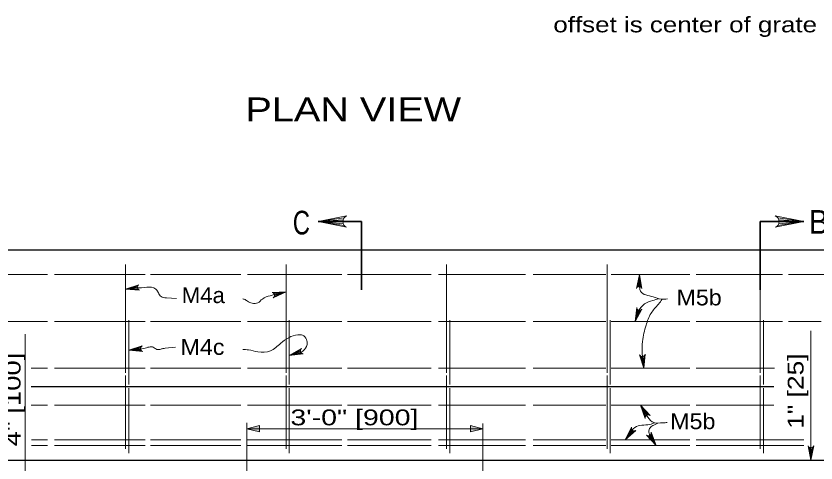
# Model space of a CAD drawing. Extents: x -1431.2 to -1397.2, y -1045.1 to -1001.1.
# Drawn here: x -1422.47 to -1414.42, y -1016.52 to -1012.02 of the extents above; entities that cross this region are included whole.
import ezdxf

# ---------------------------------------------------------------- set-up
doc = ezdxf.new("R2010")
doc.units = 0
doc.header["$LTSCALE"] = 0.064
doc.layers.add('1', color=7, linetype='Continuous', lineweight=13)

msp = doc.modelspace()

# ---------------------------------------------------------------- hatches: boundary and pattern name
at = {"layer": '1'}
for points in [[(-1420.02092, -1016.204), (-1420.147, -1016.1725), (-1420.02092, -1016.14092)], [(-1417.90083, -1016.14092), (-1417.77475, -1016.1725), (-1417.90083, -1016.204)]]:
    msp.add_hatch(color=256, dxfattribs=at).paths.add_polyline_path(points)

# ---------------------------------------------------------------- linework, layer by layer
for p, q in [((-1419.172, -1014.05292), (-1419.43075, -1014.08908)), ((-1419.18075, -1014.07083), (-1419.43075, -1014.08908)), ((-1414.80717, -1014.05292), (-1414.54842, -1014.08908)), ((-1414.79842, -1014.07083), (-1414.54842, -1014.08908)), ((-1419.18342, -1014.08908), (-1419.43075, -1014.08908)), ((-1419.17883, -1014.11233), (-1419.43075, -1014.08908)), ((-1419.16892, -1014.12908), (-1419.43075, -1014.08908)), ((-1414.81025, -1014.12908), (-1414.54842, -1014.08908)), ((-1414.80033, -1014.11233), (-1414.54842, -1014.08908)), ((-1414.79575, -1014.08908), (-1414.54842, -1014.08908)), ((-1421.36758, -1014.51992), (-1421.36758, -1015.60892)), ((-1419.75375, -1014.51992), (-1419.75375, -1015.60892)), ((-1416.52608, -1014.51992), (-1416.52608, -1015.60892)), ((-1414.98508, -1014.51992), (-1414.98508, -1015.60892)), ((-1423.05333, -1014.62258), (-1422.15367, -1014.62258)), ((-1422.08258, -1014.62258), (-1421.17017, -1014.62258)), ((-1421.119, -1014.62258), (-1420.20733, -1014.62258)), ((-1420.14183, -1014.62258), (-1419.19433, -1014.62258)), ((-1419.13675, -1014.62258), (-1418.29542, -1014.62258)), ((-1418.22033, -1014.62258), (-1417.34475, -1014.62258)), ((-1417.27042, -1014.62258), (-1416.537, -1014.62258)), ((-1416.485, -1014.62258), (-1415.69483, -1014.62258)), ((-1416.22192, -1014.74908), (-1416.19967, -1014.62258)), ((-1416.21367, -1014.7445), (-1416.19967, -1014.62258)), ((-1416.20233, -1014.7425), (-1416.19967, -1014.62258)), ((-1416.1935, -1014.744), (-1416.19967, -1014.62258)), ((-1416.18483, -1014.7485), (-1416.19967, -1014.62258)), ((-1415.631, -1014.62258), (-1414.76158, -1014.62258)), ((-1414.70258, -1014.62258), (-1413.85083, -1014.62258)), ((-1421.24533, -1014.73617), (-1421.36758, -1014.76983)), ((-1421.24842, -1014.74533), (-1421.36758, -1014.76983)), ((-1421.2485, -1014.75425), (-1421.36758, -1014.76983)), ((-1421.24492, -1014.76517), (-1421.36758, -1014.76983)), ((-1421.23908, -1014.77258), (-1421.36758, -1014.76983)), ((-1419.88183, -1014.80683), (-1419.75375, -1014.79658)), ((-1419.87533, -1014.81367), (-1419.75375, -1014.79658)), ((-1419.87192, -1014.8425), (-1419.75375, -1014.79658)), ((-1419.8705, -1014.82408), (-1419.75375, -1014.79658)), ((-1419.86983, -1014.83308), (-1419.75375, -1014.79658)), ((-1420.9565, -1014.85442), (-1420.85533, -1014.86242)), ((-1416.222, -1014.96883), (-1416.2425, -1015.094)), ((-1416.215, -1014.9755), (-1416.2425, -1015.094)), ((-1416.18625, -1014.97842), (-1416.2425, -1015.094)), ((-1416.20692, -1014.97933), (-1416.2425, -1015.094)), ((-1416.1955, -1014.98067), (-1416.2425, -1015.094)), ((-1423.05333, -1015.094), (-1422.15367, -1015.094)), ((-1422.08258, -1015.094), (-1421.17017, -1015.094)), ((-1421.33592, -1015.07958), (-1421.33592, -1015.72717)), ((-1421.119, -1015.094), (-1420.20733, -1015.094)), ((-1420.14183, -1015.094), (-1419.19433, -1015.094)), ((-1419.72208, -1015.07958), (-1419.72208, -1015.72717)), ((-1419.13675, -1015.094), (-1418.29542, -1015.094)), ((-1418.22033, -1015.094), (-1417.34475, -1015.094)), ((-1417.27042, -1015.094), (-1416.537, -1015.094)), ((-1416.49442, -1015.07958), (-1416.49442, -1015.72717)), ((-1416.485, -1015.094), (-1415.69483, -1015.094)), ((-1415.631, -1015.094), (-1414.76158, -1015.094)), ((-1414.95325, -1015.07958), (-1414.95325, -1015.72717)), ((-1414.70258, -1015.094), (-1414.37258, -1015.094)), ((-1414.47525, -1015.18883), (-1414.47525, -1016.48792)), ((-1422.37767, -1016.85133), (-1422.37767, -1015.22133)), ((-1421.21283, -1015.35125), (-1421.33592, -1015.38167)), ((-1421.21617, -1015.36033), (-1421.33592, -1015.38167)), ((-1420.96958, -1015.36383), (-1420.86583, -1015.35258)), ((-1421.2165, -1015.36925), (-1421.33592, -1015.38167)), ((-1421.21317, -1015.38025), (-1421.33592, -1015.38167)), ((-1421.2075, -1015.38792), (-1421.33592, -1015.38167)), ((-1419.60792, -1015.37992), (-1419.72208, -1015.435)), ((-1419.60933, -1015.3895), (-1419.72208, -1015.435)), ((-1419.60783, -1015.39833), (-1419.72208, -1015.435)), ((-1419.60225, -1015.40842), (-1419.72208, -1015.435)), ((-1419.59517, -1015.41467), (-1419.72208, -1015.435)), ((-1416.18658, -1015.44125), (-1416.1545, -1015.56392)), ((-1416.17742, -1015.4445), (-1416.1545, -1015.56392)), ((-1416.1685, -1015.44475), (-1416.1545, -1015.56392)), ((-1416.15758, -1015.44117), (-1416.1545, -1015.56392)), ((-1416.15008, -1015.4355), (-1416.1545, -1015.56392)), ((-1422.3185, -1015.56392), (-1422.15367, -1015.56392)), ((-1422.08258, -1015.56392), (-1421.17017, -1015.56392)), ((-1421.119, -1015.56392), (-1420.20733, -1015.56392)), ((-1420.14183, -1015.56392), (-1419.19433, -1015.56392)), ((-1419.13675, -1015.56392), (-1418.29542, -1015.56392)), ((-1418.22033, -1015.56392), (-1417.34475, -1015.56392)), ((-1417.27042, -1015.56392), (-1416.537, -1015.56392)), ((-1416.485, -1015.56392), (-1415.69483, -1015.56392)), ((-1415.631, -1015.56392), (-1414.84108, -1015.56392)), ((-1421.36758, -1015.63667), (-1421.36758, -1016.37583)), ((-1419.75375, -1015.63667), (-1419.75375, -1016.37583)), ((-1418.13992, -1015.63667), (-1418.13992, -1016.37583)), ((-1416.52608, -1015.63667), (-1416.52608, -1016.37583)), ((-1414.98508, -1015.63667), (-1414.98508, -1016.37583)), ((-1421.33592, -1015.76483), (-1421.33592, -1016.41842)), ((-1419.72208, -1015.76483), (-1419.72208, -1016.41842)), ((-1418.10825, -1015.76483), (-1418.10825, -1016.41842)), ((-1416.49442, -1015.76483), (-1416.49442, -1016.41842)), ((-1414.95325, -1015.76483), (-1414.95325, -1016.41842)), ((-1422.3185, -1015.93567), (-1422.15367, -1015.93567)), ((-1422.08258, -1015.93567), (-1421.17017, -1015.93567)), ((-1421.119, -1015.93567), (-1420.20733, -1015.93567)), ((-1420.14183, -1015.93567), (-1419.19433, -1015.93567)), ((-1419.13675, -1015.93567), (-1418.29542, -1015.93567)), ((-1418.22033, -1015.93567), (-1417.34475, -1015.93567)), ((-1417.27042, -1015.93567), (-1416.537, -1015.93567)), ((-1416.485, -1015.93567), (-1415.69483, -1015.93567)), ((-1416.12725, -1016.03767), (-1416.19042, -1015.93567)), ((-1416.13567, -1016.04542), (-1416.19042, -1015.93567)), ((-1416.14, -1016.05383), (-1416.19042, -1015.93567)), ((-1416.11892, -1016.03408), (-1416.19042, -1015.93567)), ((-1416.10933, -1016.03317), (-1416.19042, -1015.93567)), ((-1415.631, -1015.93567), (-1414.84833, -1015.93567)), ((-1420.147, -1016.69683), (-1420.147, -1016.11292)), ((-1418.73825, -1016.1725), (-1420.147, -1016.1725)), ((-1418.73825, -1016.1725), (-1417.77475, -1016.1725)), ((-1417.77475, -1016.70442), (-1417.77475, -1016.11833)), ((-1416.28025, -1016.17417), (-1416.34225, -1016.28475)), ((-1416.27592, -1016.18283), (-1416.34225, -1016.28475)), ((-1416.26967, -1016.18917), (-1416.34225, -1016.28475)), ((-1416.25925, -1016.19433), (-1416.34225, -1016.28475)), ((-1416.24992, -1016.19542), (-1416.34225, -1016.28475)), ((-1416.11267, -1016.24275), (-1416.03175, -1016.34033)), ((-1416.103, -1016.24175), (-1416.03175, -1016.34033)), ((-1416.09475, -1016.23825), (-1416.03175, -1016.34033)), ((-1416.08633, -1016.23042), (-1416.03175, -1016.34033)), ((-1416.08192, -1016.22208), (-1416.03175, -1016.34033)), ((-1422.31467, -1016.28475), (-1422.15367, -1016.28475)), ((-1422.08258, -1016.28475), (-1421.17017, -1016.28475)), ((-1421.119, -1016.28475), (-1420.20733, -1016.28475)), ((-1420.14183, -1016.28475), (-1419.19433, -1016.28475)), ((-1419.13675, -1016.28475), (-1418.29542, -1016.28475)), ((-1418.22033, -1016.28475), (-1417.34475, -1016.28475)), ((-1417.27042, -1016.28475), (-1416.537, -1016.28475)), ((-1416.485, -1016.28475), (-1415.69483, -1016.28475)), ((-1415.631, -1016.28475), (-1414.54833, -1016.28475)), ((-1422.31467, -1016.34033), (-1422.15367, -1016.34033)), ((-1422.08258, -1016.34033), (-1421.17017, -1016.34033)), ((-1421.119, -1016.34033), (-1420.20733, -1016.34033)), ((-1420.14183, -1016.34033), (-1419.19433, -1016.34033)), ((-1419.13675, -1016.34033), (-1418.29542, -1016.34033)), ((-1418.22033, -1016.34033), (-1417.34475, -1016.34033)), ((-1417.27042, -1016.34033), (-1416.537, -1016.34033)), ((-1416.485, -1016.34033), (-1415.69483, -1016.34033)), ((-1415.631, -1016.34033), (-1414.54833, -1016.34033)), ((-1414.49333, -1016.35858), (-1414.47525, -1016.48792)), ((-1414.48433, -1016.36292), (-1414.47525, -1016.48792)), ((-1414.45525, -1016.357), (-1414.47525, -1016.48792)), ((-1414.46358, -1016.362), (-1414.47525, -1016.48792)), ((-1414.47525, -1016.36425), (-1414.47525, -1016.48792)), ((-1411.08033, -1016.48792), (-1414.53833, -1016.48792))]:
    msp.add_line(p, q, dxfattribs=at)
at = {"layer": '1', "lineweight": 35}
for q in [(-1419.43075, -1014.08908), (-1418.99408, -1014.77492)]:
    msp.add_line((-1418.99408, -1014.08908), q, dxfattribs=at)
at = {"layer": '1', "lineweight": 25}
for p, q in [((-1426.97542, -1014.3715), (-1411.01725, -1014.3715)), ((-1422.3185, -1015.74883), (-1414.8475, -1015.74883)), ((-1426.94317, -1016.48792), (-1414.14858, -1016.48792))]:
    msp.add_line(p, q, dxfattribs=at)
at = {"layer": '1'}
for points in [[(-1419.14492, -1014.14625), (-1419.43075, -1014.08908), (-1419.14492, -1014.03192)], [(-1414.83425, -1014.14625), (-1414.54842, -1014.08908), (-1414.83425, -1014.03192)], [(-1418.13992, -1014.51992), (-1418.13992, -1015.16475), (-1418.13992, -1015.60892)], [(-1416.23042, -1014.76058), (-1416.19967, -1014.62258), (-1416.175, -1014.76175)], [(-1421.22642, -1014.77933), (-1421.36758, -1014.76983), (-1421.23358, -1014.72433)], [(-1419.89508, -1014.80142), (-1419.75375, -1014.79658), (-1419.88233, -1014.85542)], [(-1416.17492, -1014.96975), (-1416.2425, -1015.094), (-1416.22792, -1014.95333)], [(-1418.10825, -1015.07958), (-1418.10825, -1015.42817), (-1418.10825, -1015.72717)], [(-1421.19508, -1015.39492), (-1421.33592, -1015.38167), (-1421.20083, -1015.33975)], [(-1419.5815, -1015.419), (-1419.72208, -1015.435), (-1419.5985, -1015.36625)], [(-1416.14317, -1015.42292), (-1416.1545, -1015.56392), (-1416.19825, -1015.42942)], [(-1416.14092, -1016.06808), (-1416.19042, -1015.93567), (-1416.09383, -1016.03892)], [(-1416.23625, -1016.19117), (-1416.34225, -1016.28475), (-1416.28042, -1016.15758)], [(-1416.081, -1016.20775), (-1416.03175, -1016.34033), (-1416.12817, -1016.23683)], [(-1414.44667, -1016.345), (-1414.47525, -1016.48792), (-1414.50383, -1016.345)]]:
    msp.add_lwpolyline(points, dxfattribs=at)
at = {"layer": '1', "lineweight": 35}
msp.add_lwpolyline([(-1414.98508, -1014.77492), (-1414.98508, -1014.08908), (-1414.54842, -1014.08908)], dxfattribs=at)
at = {"layer": '1'}
for points in [[(-1420.02092, -1016.204), (-1420.147, -1016.1725), (-1420.02092, -1016.14092)], [(-1417.90083, -1016.14092), (-1417.77475, -1016.1725), (-1417.90083, -1016.204)]]:
    msp.add_lwpolyline(points, close=True, dxfattribs=at)
for centre, radius, start, end in [((-1419.12186, -1014.08904), 0.06168, 112.08782, 247.91395), ((-1414.8573, -1014.08904), 0.06168, 292.08605, 67.91218), ((-1414.47526, -1016.33349), 0.03084, 202.08782, 337.91395)]:
    msp.add_arc(centre, radius, start, end, dxfattribs=at)
for centre, major_axis, start_param, end_param in [((-1421.21888, -1014.75041), (-0.02993, 0), 5.2280036, 7.5986167), ((-1419.8997, -1014.83095), (0.02993, 0), 5.3289382, 7.6995514), ((-1416.20297, -1014.77244), (0.02993, 0), 0.3633246, 2.7339377), ((-1416.19804, -1014.95081), (-0.02993, 0), 0.084585, 2.4551981), ((-1421.18674, -1015.36621), (-0.02993, 0), 5.2009606, 7.5715737), ((-1419.5793, -1015.38919), (-0.02993, 0), 5.4085471, 7.7791602), ((-1416.17203, -1015.41501), (-0.02993, 0), 0.5029452, 2.8735583), ((-1416.11144, -1016.06309), (0.02993, 0), 0.940338, 3.3109511), ((-1416.25151, -1016.1654), (-0.02993, 0), 6.0185309, 8.389144), ((-1416.11048, -1016.21275), (-0.02993, 0), 0.9383465, 3.3089596)]:
    msp.add_ellipse(centre, major_axis=major_axis, ratio=0.999895, start_param=start_param, end_param=end_param, dxfattribs=at)
for points in [[(-1415.91883, -1014.86725), (-1415.98083, -1014.87), (-1416.06175, -1014.84625), (-1416.18808, -1014.79017), (-1416.19908, -1014.75008), (-1416.20142, -1014.70133), (-1416.19967, -1014.62258)], [(-1420.95625, -1014.85442), (-1420.9895, -1014.85225), (-1421.02733, -1014.8255), (-1421.04725, -1014.78767), (-1421.08283, -1014.75658), (-1421.18058, -1014.75208), (-1421.28275, -1014.75875), (-1421.36758, -1014.76983)], [(-1420.1895, -1014.86725), (-1420.17425, -1014.87), (-1420.14325, -1014.89), (-1420.09433, -1014.91008), (-1420.03875, -1014.90558), (-1419.99208, -1014.86775), (-1419.91442, -1014.83442), (-1419.75375, -1014.79658)], [(-1416.00683, -1014.86692), (-1416.0665, -1014.882), (-1416.14975, -1014.91775), (-1416.20917, -1014.98675), (-1416.2425, -1015.094)], [(-1415.97125, -1014.86958), (-1416.00942, -1014.92008), (-1416.08308, -1015.01058), (-1416.13308, -1015.13208), (-1416.16875, -1015.294), (-1416.17117, -1015.42258), (-1416.1545, -1015.56392)], [(-1420.1895, -1015.37467), (-1420.13208, -1015.37942), (-1420.03658, -1015.39942), (-1419.91217, -1015.3905), (-1419.80775, -1015.31267), (-1419.6345, -1015.22817), (-1419.58783, -1015.23258), (-1419.54783, -1015.27483), (-1419.54342, -1015.326), (-1419.58342, -1015.3905), (-1419.72208, -1015.435)], [(-1420.96958, -1015.36383), (-1420.99175, -1015.366), (-1421.02283, -1015.375), (-1421.05392, -1015.375), (-1421.0895, -1015.35275), (-1421.1295, -1015.3505), (-1421.18508, -1015.366), (-1421.33592, -1015.38167)], [(-1415.9225, -1016.11058), (-1415.96042, -1016.11292), (-1416.07192, -1016.10225), (-1416.12767, -1016.037), (-1416.19042, -1015.93567)], [(-1416.04508, -1016.11225), (-1416.09558, -1016.12842), (-1416.24617, -1016.15925), (-1416.30192, -1016.23167), (-1416.34225, -1016.28475)], [(-1416.01575, -1016.11575), (-1416.02958, -1016.12292), (-1416.05642, -1016.13592), (-1416.08908, -1016.1585), (-1416.10292, -1016.18392), (-1416.1, -1016.22975), (-1416.03175, -1016.34033)]]:
    msp.add_spline(points, degree=3, dxfattribs=at)

# ---------------------------------------------------------------- texts
for s, height, width, p in [('offset is center of grate', 0.156, 1.25, (-1417.06625, -1012.1855)), ('PLAN VIEW', 0.2382, 1.25, (-1420.16225, -1013.07908)), ('C', 0.2382, 0.75, (-1419.68625, -1014.21867)), ('B', 0.2382, 0.95, (-1414.49633, -1014.21092)), ('M4a', 0.1588, 1.05, (-1420.80333, -1014.90908)), ('M5b', 0.1588, 1.1, (-1415.827, -1014.93192)), ('M4c', 0.1588, 1.1, (-1420.815, -1015.42975)), ('3\'-0" [900]', 0.1588, 1.35, (-1419.71075, -1016.13817)), ('M5b', 0.1588, 1.1, (-1415.89042, -1016.177))]:
    msp.add_text(s, height=height, dxfattribs=dict(at, width=width)).set_placement(p)
for s, width, p in [('4" [100]', 1.3, (-1422.42467, -1016.34992)), ('1" [25]', 1.25, (-1414.54992, -1016.17325))]:
    msp.add_text(s, height=0.1588, rotation=90, dxfattribs=dict(at, width=width)).set_placement(p)

doc.saveas('drawing.dxf')
